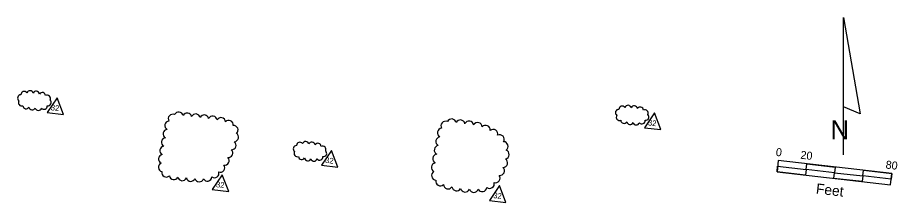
# Model space of a CAD drawing. Extents: x 926540 to 927877, y 636188 to 637075.
# Drawn here: x 927262 to 927877, y 636859 to 636988 of the extents above; entities that cross this region are included whole.
import ezdxf

# ---------------------------------------------------------------- set-up
doc = ezdxf.new("R2010")
doc.units = 0
for name, color, linetype in [('Cloud_dp', 7, 'Continuous'), ('NorthArw_dp', 7, 'Continuous'), ('Scale_dp', 7, 'Continuous')]:
    doc.layers.add(name, color=color, linetype=linetype)

msp = doc.modelspace()

# ---------------------------------------------------------------- linework, layer by layer
at = {"layer": 'Cloud_dp'}
for points in [[(927289.2, 636932.1), (927282.19, 636921.71), (927293.67, 636920.39)], [(927707.16, 636921.54), (927700.15, 636911.15), (927711.63, 636909.83)], [(927481.22, 636895.34), (927474.21, 636884.95), (927485.69, 636883.63)], [(927404.81, 636878.29), (927397.8, 636867.9), (927409.28, 636866.58)], [(927598.85, 636870.69), (927591.84, 636860.29), (927603.32, 636858.97)]]:
    msp.add_lwpolyline(points, close=True, dxfattribs=at)
for centre, radius, start, end in [((927263.84, 636931.89), 2.31, 88.74525, 233.74525), ((927266.2, 636934.23), 2.31, 35.92386, 180.92386), ((927270.23, 636934.78), 2.31, 14.50632, 159.50632), ((927274.55, 636934.36), 2.31, 9.41904, 154.41904), ((927278.77, 636933.5), 2.31, 2.54325, 147.54325), ((927282.17, 636931.57), 2.31, 333.28416, 118.28416), ((927264.38, 636928.73), 2.31, 145.78075, 290.78075), ((927267.5, 636926.74), 2.31, 184.25215, 329.25215), ((927271.77, 636925.93), 2.31, 189.2335, 334.2335), ((927280.02, 636926.38), 2.31, 219.67619, 4.67619), ((927282.65, 636928.85), 2.31, 261.79822, 46.79822), ((927684.61, 636924.02), 2.31, 35.92386, 180.92386), ((927688.64, 636924.57), 2.31, 14.50632, 159.50632), ((927692.96, 636924.15), 2.31, 9.41904, 154.41904), ((927697.18, 636923.29), 2.31, 2.54325, 147.54325), ((927276.05, 636925.61), 2.31, 197.12777, 342.12777), ((927370.12, 636917.46), 3.14, 65.30132, 210.30132), ((927374.3, 636919.03), 3.14, 10.93299, 155.93299), ((927380.24, 636918.34), 3.14, 10.93299, 155.93299), ((927386.19, 636917.66), 3.14, 10.93299, 155.93299), ((927392.14, 636916.97), 3.14, 10.9314, 155.9314), ((927398.05, 636916.2), 3.14, 9.12977, 154.12977), ((927682.25, 636921.68), 2.31, 88.74525, 233.74525), ((927682.79, 636918.52), 2.31, 145.78075, 290.78075), ((927700.58, 636921.36), 2.31, 333.28416, 118.28416), ((927701.06, 636918.64), 2.31, 261.79822, 46.79822), ((927367.72, 636912.75), 3.14, 95.77477, 240.77477), ((927403.84, 636915.08), 3.14, 4.04594, 149.04594), ((927409.29, 636913.18), 3.14, 352.52091, 137.52091), ((927561.01, 636912.48), 3.23, 65.86297, 210.86297), ((927565.28, 636914.11), 3.23, 10.93299, 155.93299), ((927571.4, 636913.4), 3.23, 10.93299, 155.93299), ((927577.5, 636912.66), 3.23, 10.11137, 155.11137), ((927583.44, 636911.53), 3.23, 3.37416, 148.37416), ((927685.91, 636916.53), 2.31, 184.25215, 329.25215), ((927690.18, 636915.72), 2.31, 189.2335, 334.2335), ((927694.46, 636915.4), 2.31, 197.12777, 342.12777), ((927698.43, 636916.17), 2.31, 219.67619, 4.67619), ((927366.51, 636906.88), 3.14, 95.77477, 240.77477), ((927412.66, 636909.64), 3.14, 309.61767, 94.61767), ((927413.01, 636904.55), 3.14, 273.41069, 58.41069), ((927558.62, 636907.61), 3.23, 96.82746, 241.82746), ((927589.11, 636909.62), 3.23, 354.35853, 139.35853), ((927594.38, 636906.8), 3.23, 344.37277, 129.37277), ((927365.31, 636901.02), 3.14, 96.11412, 241.11412), ((927411.27, 636898.94), 3.14, 266.9813, 51.9813), ((927459.1, 636898.7), 2.31, 35.92386, 180.92386), ((927463.13, 636899.24), 2.31, 14.50632, 159.50632), ((927467.44, 636898.82), 2.31, 9.41904, 154.41904), ((927557.48, 636901.56), 3.23, 96.83691, 241.83691), ((927598.85, 636903), 3.23, 329.87102, 114.87102), ((927601.63, 636898.15), 3.23, 304.72138, 89.72138), ((927364.2, 636895.16), 3.14, 97.43441, 242.43441), ((927409.02, 636893.46), 3.14, 263.41693, 48.41693), ((927456.74, 636896.35), 2.31, 88.74525, 233.74525), ((927471.67, 636897.96), 2.31, 2.54325, 147.54325), ((927475.07, 636896.03), 2.31, 333.28416, 118.28416), ((927475.55, 636893.31), 2.31, 261.79822, 46.79822), ((927556.35, 636895.5), 3.23, 97.09717, 242.09717), ((927602.28, 636892.49), 3.23, 283.46502, 68.46502), ((927363.29, 636889.29), 3.14, 100.06638, 245.06638), ((927406.44, 636888.12), 3.14, 260.02126, 45.02126), ((927457.28, 636893.19), 2.31, 145.78075, 290.78075), ((927460.4, 636891.21), 2.31, 184.25215, 329.25215), ((927464.66, 636890.4), 2.31, 189.2335, 334.2335), ((927468.95, 636890.08), 2.31, 197.12777, 342.12777), ((927472.92, 636890.84), 2.31, 219.67619, 4.67619), ((927555.27, 636889.45), 3.23, 97.63561, 242.63561), ((927601.2, 636886.69), 3.23, 270.3602, 55.3602), ((927363.19, 636883.55), 3.14, 112.94946, 257.94946), ((927403.33, 636883.22), 3.14, 250.29071, 35.29071), ((927554.28, 636883.38), 3.23, 98.70827, 243.70827), ((927599.02, 636881.08), 3.23, 262.30142, 47.30142), ((927365.61, 636879.83), 3.14, 168.02484, 313.02484), ((927370.86, 636878.01), 3.14, 188.64971, 333.64971), ((927376.74, 636877.28), 3.14, 192.24861, 337.24861), ((927382.68, 636876.81), 3.14, 193.70107, 338.70107), ((927394.31, 636876.99), 3.14, 210.13506, 355.13506), ((927399.3, 636879.26), 3.14, 233.64566, 18.64566), ((927554.47, 636877.69), 3.23, 120.12823, 265.12823), ((927596, 636875.96), 3.23, 251.52994, 36.52994), ((927388.64, 636876.49), 3.14, 195.1195, 340.1195), ((927557.35, 636873.81), 3.23, 168.06051, 313.06051), ((927562.79, 636871.58), 3.23, 182.30943, 327.30943), ((927591.89, 636871.92), 3.23, 232.46956, 17.46956), ((927568.71, 636870.26), 3.23, 187.5902, 332.5902), ((927574.74, 636869.43), 3.23, 191.77982, 336.77982), ((927580.78, 636869.15), 3.23, 197.87274, 342.87274), ((927586.71, 636869.73), 3.23, 208.37848, 353.37848)]:
    msp.add_arc(centre, radius, start, end, dxfattribs=at)
at = {"layer": 'NorthArw_dp'}
msp.add_line((927839.54, 636892.17), (927839.54, 636988.17), dxfattribs=at)
msp.add_lwpolyline([(927839.54, 636925.77), (927839.54, 636988.17), (927851.06, 636920.97)], close=True, dxfattribs=at)
at = {"layer": 'Scale_dp'}
for p, q in [((927793.9, 636888.29), (927792.98, 636880.34)), ((927873.37, 636879.14), (927793.9, 636888.29)), ((927792.98, 636880.34), (927872.46, 636871.19)), ((927872.46, 636871.19), (927873.37, 636879.14))]:
    msp.add_line(p, q, dxfattribs=at)
for points in [[(927792.98, 636880.34), (927793.44, 636884.31), (927813.31, 636882.03), (927812.85, 636878.05)], [(927813.31, 636882.03), (927813.77, 636886), (927833.64, 636883.71), (927833.18, 636879.74)], [(927832.72, 636875.76), (927833.18, 636879.74), (927853.05, 636877.45), (927852.59, 636873.48)], [(927853.05, 636877.45), (927853.5, 636881.42), (927873.37, 636879.14), (927872.92, 636875.16)]]:
    msp.add_lwpolyline(points, close=True, dxfattribs=at)

# ---------------------------------------------------------------- texts
at = {"layer": 'Cloud_dp'}
for p in [(927284.62, 636923.42), (927702.58, 636912.86), (927476.64, 636886.66), (927400.23, 636869.61), (927594.27, 636862.01)]:
    msp.add_text('32', height=3.938, rotation=353.43299, dxfattribs=at).set_placement(p)
at = {"layer": 'NorthArw_dp'}
msp.add_text('N', height=13.43, dxfattribs=at).set_placement((927830.41, 636903.03))
at = {"layer": 'Scale_dp'}
for s, height, p in [('0', 5.6, (927791.93, 636891.53)), ('20', 5.6, (927809.18, 636889.55)), ('80', 5.6, (927868.77, 636882.69)), ('Feet', 7.2, (927819.97, 636865.15))]:
    msp.add_text(s, height=height, rotation=353.43299, dxfattribs=at).set_placement(p)

doc.saveas('drawing.dxf')
